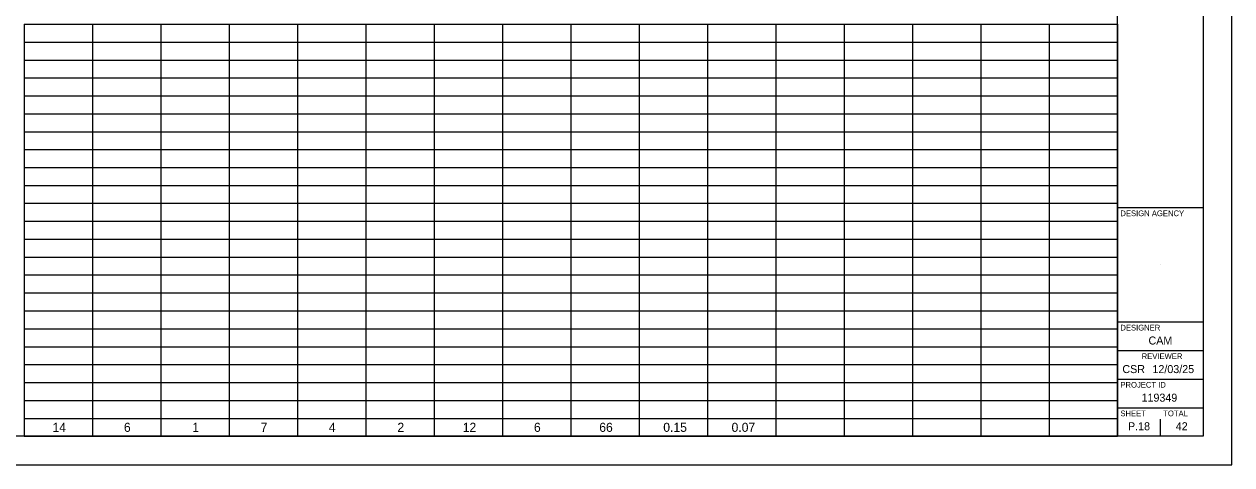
# Model space of a CAD drawing. Extents: x 0 to 34, y 0 to 22.
# Drawn here: x 12.87 to 34, y 0 to 7.71 of the extents above; entities that cross this region are included whole.
import ezdxf

# ---------------------------------------------------------------- set-up
doc = ezdxf.new("R2010")
doc.units = 0
for name, color, linetype in [('SH_Border', 7, 'Continuous'), ('SH_Cut_Line', 7, 'Continuous'), ('SH_Data', 7, 'Continuous'), ('SH_Text', 7, 'Continuous')]:
    doc.layers.add(name, color=color, linetype=linetype)

msp = doc.modelspace()

# ---------------------------------------------------------------- linework, layer by layer
at = {"layer": 'SH_Border'}
for p, q in [((32, 0.5), (32, 21.5)), ((32, 4.5), (33.5, 4.5)), ((32, 2.5), (33.5, 2.5)), ((32, 2), (33.5, 2)), ((32, 1.5), (33.5, 1.5)), ((32, 1), (33.5, 1))]:
    msp.add_line(p, q, dxfattribs=at)
msp.add_lwpolyline([(1.5, 21.5), (33.5, 21.5), (33.5, 0.5), (1.5, 0.5)], close=True, dxfattribs=at)
at = {"layer": 'SH_Cut_Line'}
msp.add_lwpolyline([(0, 0), (34, 0), (34, 22), (0, 22)], close=True, dxfattribs=at)
at = {"layer": 'SH_Data'}
for p, q in [((32.75, 3.5), (32.75, 3.5)), ((32.375, 0.675), (32.375, 0.675)), ((32.75, 0.5), (32.75, 0.8))]:
    msp.add_line(p, q, dxfattribs=at)
at = {"layer": 'SH_Text'}
for p, q in [((12.867, 7.709), (14.063, 7.709)), ((12.867, 7.709), (12.867, 6.769)), ((14.063, 7.709), (16.454, 7.709)), ((14.063, 7.709), (14.063, 6.769)), ((15.259, 7.709), (15.259, 6.769)), ((16.454, 7.709), (23.629, 7.709)), ((16.454, 7.709), (16.454, 6.769)), ((17.65, 7.709), (17.65, 6.769)), ((18.846, 7.709), (18.846, 6.769)), ((20.042, 7.709), (20.042, 6.769)), ((21.238, 7.709), (21.238, 6.769)), ((22.434, 7.709), (22.434, 6.769)), ((23.629, 7.709), (24.825, 7.709)), ((23.629, 7.709), (23.629, 6.769)), ((24.825, 7.709), (26.021, 7.709)), ((24.825, 7.709), (24.825, 6.769)), ((26.021, 7.709), (28.413, 7.709)), ((26.021, 7.709), (26.021, 6.769)), ((27.217, 7.709), (27.217, 6.769)), ((28.413, 7.709), (30.804, 7.709)), ((28.413, 7.709), (28.413, 6.769)), ((29.608, 7.709), (29.608, 6.769)), ((30.804, 7.709), (32, 7.709)), ((30.804, 7.709), (30.804, 6.769)), ((32, 7.709), (32, 6.769)), ((12.867, 7.396), (14.063, 7.396)), ((14.063, 7.396), (16.454, 7.396)), ((16.454, 7.396), (23.629, 7.396)), ((23.629, 7.396), (24.825, 7.396)), ((24.825, 7.396), (26.021, 7.396)), ((26.021, 7.396), (28.413, 7.396)), ((28.413, 7.396), (30.804, 7.396)), ((30.804, 7.396), (32, 7.396)), ((12.867, 7.082), (14.063, 7.082)), ((14.063, 7.082), (16.454, 7.082)), ((16.454, 7.082), (23.629, 7.082)), ((23.629, 7.082), (24.825, 7.082)), ((24.825, 7.082), (26.021, 7.082)), ((26.021, 7.082), (28.413, 7.082)), ((28.413, 7.082), (30.804, 7.082)), ((30.804, 7.082), (32, 7.082)), ((12.867, 6.769), (14.063, 6.769)), ((12.867, 6.769), (12.867, 6.142)), ((14.063, 6.769), (16.454, 6.769)), ((14.063, 6.769), (14.063, 6.142)), ((15.259, 6.769), (15.259, 6.142)), ((16.454, 6.769), (23.629, 6.769)), ((16.454, 6.769), (16.454, 6.142)), ((17.65, 6.769), (17.65, 6.142)), ((18.846, 6.769), (18.846, 6.142)), ((20.042, 6.769), (20.042, 6.142)), ((21.238, 6.769), (21.238, 6.142)), ((22.434, 6.769), (22.434, 6.142)), ((23.629, 6.769), (24.825, 6.769)), ((23.629, 6.769), (23.629, 6.142)), ((24.825, 6.769), (26.021, 6.769)), ((24.825, 6.769), (24.825, 6.142)), ((26.021, 6.769), (28.413, 6.769)), ((26.021, 6.769), (26.021, 6.142)), ((27.217, 6.769), (27.217, 6.142)), ((28.413, 6.769), (30.804, 6.769)), ((28.413, 6.769), (28.413, 6.142)), ((29.608, 6.769), (29.608, 6.142)), ((30.804, 6.769), (32, 6.769)), ((30.804, 6.769), (30.804, 6.142)), ((32, 6.769), (32, 6.142)), ((12.867, 6.455), (14.063, 6.455)), ((14.063, 6.455), (16.454, 6.455)), ((16.454, 6.455), (23.629, 6.455)), ((23.629, 6.455), (24.825, 6.455)), ((24.825, 6.455), (26.021, 6.455)), ((26.021, 6.455), (28.413, 6.455)), ((28.413, 6.455), (30.804, 6.455)), ((30.804, 6.455), (32, 6.455)), ((12.867, 6.142), (14.063, 6.142)), ((12.867, 6.142), (12.867, 5.201)), ((14.063, 6.142), (16.454, 6.142)), ((14.063, 6.142), (14.063, 5.201)), ((15.259, 6.142), (15.259, 5.201)), ((16.454, 6.142), (23.629, 6.142)), ((16.454, 6.142), (16.454, 5.201)), ((17.65, 6.142), (17.65, 5.201)), ((18.846, 6.142), (18.846, 5.201)), ((20.042, 6.142), (20.042, 5.201)), ((21.238, 6.142), (21.238, 5.201)), ((22.434, 6.142), (22.434, 5.201)), ((23.629, 6.142), (24.825, 6.142)), ((23.629, 6.142), (23.629, 5.201)), ((24.825, 6.142), (26.021, 6.142)), ((24.825, 6.142), (24.825, 5.201)), ((26.021, 6.142), (28.413, 6.142)), ((26.021, 6.142), (26.021, 5.201)), ((27.217, 6.142), (27.217, 5.201)), ((28.413, 6.142), (30.804, 6.142)), ((28.413, 6.142), (28.413, 5.201)), ((29.608, 6.142), (29.608, 5.201)), ((30.804, 6.142), (32, 6.142)), ((30.804, 6.142), (30.804, 5.201)), ((32, 6.142), (32, 5.201)), ((12.867, 5.828), (14.063, 5.828)), ((14.063, 5.828), (16.454, 5.828)), ((16.454, 5.828), (23.629, 5.828)), ((23.629, 5.828), (24.825, 5.828)), ((24.825, 5.828), (26.021, 5.828)), ((26.021, 5.828), (28.413, 5.828)), ((28.413, 5.828), (30.804, 5.828)), ((30.804, 5.828), (32, 5.828)), ((12.867, 5.515), (14.063, 5.515)), ((14.063, 5.515), (16.454, 5.515)), ((16.454, 5.515), (23.629, 5.515)), ((23.629, 5.515), (24.825, 5.515)), ((24.825, 5.515), (26.021, 5.515)), ((26.021, 5.515), (28.413, 5.515)), ((28.413, 5.515), (30.804, 5.515)), ((30.804, 5.515), (32, 5.515)), ((12.867, 5.201), (14.063, 5.201)), ((12.867, 5.201), (12.867, 4.575)), ((14.063, 5.201), (16.454, 5.201)), ((14.063, 5.201), (14.063, 4.575)), ((15.259, 5.201), (15.259, 4.575)), ((16.454, 5.201), (23.629, 5.201)), ((16.454, 5.201), (16.454, 4.575)), ((17.65, 5.201), (17.65, 4.575)), ((18.846, 5.201), (18.846, 4.575)), ((20.042, 5.201), (20.042, 4.575)), ((21.238, 5.201), (21.238, 4.575)), ((22.434, 5.201), (22.434, 4.575)), ((23.629, 5.201), (24.825, 5.201)), ((23.629, 5.201), (23.629, 4.575)), ((24.825, 5.201), (26.021, 5.201)), ((24.825, 5.201), (24.825, 4.575)), ((26.021, 5.201), (28.413, 5.201)), ((26.021, 5.201), (26.021, 4.575)), ((27.217, 5.201), (27.217, 4.575)), ((28.413, 5.201), (30.804, 5.201)), ((28.413, 5.201), (28.413, 4.575)), ((29.608, 5.201), (29.608, 4.575)), ((30.804, 5.201), (32, 5.201)), ((30.804, 5.201), (30.804, 4.575)), ((32, 5.201), (32, 4.575)), ((12.867, 4.888), (14.063, 4.888)), ((14.063, 4.888), (16.454, 4.888)), ((16.454, 4.888), (23.629, 4.888)), ((23.629, 4.888), (24.825, 4.888)), ((24.825, 4.888), (26.021, 4.888)), ((26.021, 4.888), (28.413, 4.888)), ((28.413, 4.888), (30.804, 4.888)), ((30.804, 4.888), (32, 4.888)), ((12.867, 4.575), (14.063, 4.575)), ((12.867, 4.575), (12.867, 0.5)), ((14.063, 4.575), (16.454, 4.575)), ((14.063, 4.575), (14.063, 0.5)), ((15.259, 4.575), (15.259, 0.5)), ((16.454, 4.575), (23.629, 4.575)), ((16.454, 4.575), (16.454, 0.5)), ((17.65, 4.575), (17.65, 0.813)), ((18.846, 4.575), (18.846, 0.5)), ((20.042, 4.575), (20.042, 0.5)), ((21.238, 4.575), (21.238, 0.5)), ((22.434, 4.575), (22.434, 0.5)), ((23.629, 4.575), (24.825, 4.575)), ((23.629, 4.575), (23.629, 0.5)), ((24.825, 4.575), (26.021, 4.575)), ((24.825, 4.575), (24.825, 0.5)), ((26.021, 4.575), (28.413, 4.575)), ((26.021, 4.575), (26.021, 0.5)), ((27.217, 4.575), (27.217, 0.5)), ((28.413, 4.575), (30.804, 4.575)), ((28.413, 4.575), (28.413, 0.5)), ((29.608, 4.575), (29.608, 0.5)), ((30.804, 4.575), (32, 4.575)), ((30.804, 4.575), (30.804, 0.5)), ((32, 4.575), (32, 0.5)), ((12.867, 4.261), (14.063, 4.261)), ((14.063, 4.261), (16.454, 4.261)), ((16.454, 4.261), (23.629, 4.261)), ((23.629, 4.261), (24.825, 4.261)), ((24.825, 4.261), (26.021, 4.261)), ((26.021, 4.261), (28.413, 4.261)), ((28.413, 4.261), (30.804, 4.261)), ((30.804, 4.261), (32, 4.261)), ((12.867, 3.948), (14.063, 3.948)), ((14.063, 3.948), (16.454, 3.948)), ((16.454, 3.948), (23.629, 3.948)), ((23.629, 3.948), (24.825, 3.948)), ((24.825, 3.948), (26.021, 3.948)), ((26.021, 3.948), (28.413, 3.948)), ((28.413, 3.948), (30.804, 3.948)), ((30.804, 3.948), (32, 3.948)), ((12.867, 3.634), (14.063, 3.634)), ((14.063, 3.634), (16.454, 3.634)), ((16.454, 3.634), (23.629, 3.634)), ((23.629, 3.634), (24.825, 3.634)), ((24.825, 3.634), (26.021, 3.634)), ((26.021, 3.634), (28.413, 3.634)), ((28.413, 3.634), (30.804, 3.634)), ((30.804, 3.634), (32, 3.634)), ((12.867, 3.321), (14.063, 3.321)), ((14.063, 3.321), (16.454, 3.321)), ((16.454, 3.321), (23.629, 3.321)), ((23.629, 3.321), (24.825, 3.321)), ((24.825, 3.321), (26.021, 3.321)), ((26.021, 3.321), (28.413, 3.321)), ((28.413, 3.321), (30.804, 3.321)), ((30.804, 3.321), (32, 3.321)), ((12.867, 3.007), (14.063, 3.007)), ((14.063, 3.007), (16.454, 3.007)), ((16.454, 3.007), (23.629, 3.007)), ((23.629, 3.007), (24.825, 3.007)), ((24.825, 3.007), (26.021, 3.007)), ((26.021, 3.007), (28.413, 3.007)), ((28.413, 3.007), (30.804, 3.007)), ((30.804, 3.007), (32, 3.007)), ((12.867, 2.694), (14.063, 2.694)), ((14.063, 2.694), (16.454, 2.694)), ((16.454, 2.694), (23.629, 2.694)), ((23.629, 2.694), (24.825, 2.694)), ((24.825, 2.694), (26.021, 2.694)), ((26.021, 2.694), (28.413, 2.694)), ((28.413, 2.694), (30.804, 2.694)), ((30.804, 2.694), (32, 2.694)), ((12.867, 2.381), (14.063, 2.381)), ((14.063, 2.381), (16.454, 2.381)), ((16.454, 2.381), (23.629, 2.381)), ((23.629, 2.381), (24.825, 2.381)), ((24.825, 2.381), (26.021, 2.381)), ((26.021, 2.381), (28.413, 2.381)), ((28.413, 2.381), (30.804, 2.381)), ((30.804, 2.381), (32, 2.381)), ((12.867, 2.067), (14.063, 2.067)), ((14.063, 2.067), (16.454, 2.067)), ((16.454, 2.067), (23.629, 2.067)), ((23.629, 2.067), (24.825, 2.067)), ((24.825, 2.067), (26.021, 2.067)), ((26.021, 2.067), (28.413, 2.067)), ((28.413, 2.067), (30.804, 2.067)), ((30.804, 2.067), (32, 2.067)), ((12.867, 1.754), (14.063, 1.754)), ((14.063, 1.754), (16.454, 1.754)), ((16.454, 1.754), (23.629, 1.754)), ((23.629, 1.754), (24.825, 1.754)), ((24.825, 1.754), (26.021, 1.754)), ((26.021, 1.754), (28.413, 1.754)), ((28.413, 1.754), (30.804, 1.754)), ((30.804, 1.754), (32, 1.754)), ((12.867, 1.44), (14.063, 1.44)), ((14.063, 1.44), (16.454, 1.44)), ((16.454, 1.44), (23.629, 1.44)), ((23.629, 1.44), (24.825, 1.44)), ((24.825, 1.44), (26.021, 1.44)), ((26.021, 1.44), (28.413, 1.44)), ((28.413, 1.44), (30.804, 1.44)), ((30.804, 1.44), (32, 1.44)), ((12.867, 1.127), (14.063, 1.127)), ((14.063, 1.127), (16.454, 1.127)), ((16.454, 1.127), (23.629, 1.127)), ((23.629, 1.127), (24.825, 1.127)), ((24.825, 1.127), (26.021, 1.127)), ((26.021, 1.127), (28.413, 1.127)), ((28.413, 1.127), (30.804, 1.127)), ((30.804, 1.127), (32, 1.127)), ((12.867, 0.813), (14.063, 0.813)), ((14.063, 0.813), (16.454, 0.813)), ((16.454, 0.813), (23.629, 0.813)), ((17.65, 0.813), (17.65, 0.5)), ((23.629, 0.813), (24.825, 0.813)), ((24.825, 0.813), (26.021, 0.813)), ((26.021, 0.813), (28.413, 0.813)), ((28.413, 0.813), (30.804, 0.813)), ((30.804, 0.813), (32, 0.813)), ((12.867, 0.5), (14.063, 0.5)), ((14.063, 0.5), (16.454, 0.5)), ((16.454, 0.5), (23.629, 0.5)), ((23.629, 0.5), (24.825, 0.5)), ((24.825, 0.5), (26.021, 0.5)), ((26.021, 0.5), (28.413, 0.5)), ((28.413, 0.5), (30.804, 0.5)), ((30.804, 0.5), (32, 0.5))]:
    msp.add_line(p, q, dxfattribs=at)

# ---------------------------------------------------------------- texts
at = {"layer": 'SH_Data'}
for s, height, p in [('DESIGN AGENCY', 0.1, (32.05, 4.35)), ('DESIGNER', 0.1, (32.05, 2.35)), ('CAM', 0.14, (32.542, 2.105)), ('REVIEWER', 0.1, (32.422, 1.85)), ('CSR', 0.14, (32.085, 1.605)), ('12/03/25', 0.14, (32.611, 1.605)), ('PROJECT ID', 0.1, (32.05, 1.35)), ('119349', 0.14, (32.42, 1.105)), ('SHEET', 0.1, (32.05, 0.85)), ('TOTAL', 0.1, (32.8, 0.85)), ('P.18', 0.14, (32.183, 0.605)), ('42', 0.14, (33.019, 0.605))]:
    msp.add_text(s, height=height, dxfattribs=at).set_placement(p)
at = {"layer": 'SH_Text'}
for s, height, p in [('14', 0.1586, (13.363, 0.577)), ('6', 0.159, (14.613, 0.577)), ('1', 0.159, (15.81, 0.577)), ('7', 0.159, (17.005, 0.577)), ('4', 0.159, (18.199, 0.577)), ('2', 0.159, (19.398, 0.577)), ('12', 0.1586, (20.542, 0.577)), ('6', 0.159, (21.788, 0.577)), ('66', 0.1586, (22.931, 0.577)), ('0.15', 0.1586, (24.051, 0.577)), ('0.07', 0.1586, (25.246, 0.577))]:
    msp.add_text(s, height=height, dxfattribs=at).set_placement(p)

doc.saveas('drawing.dxf')
